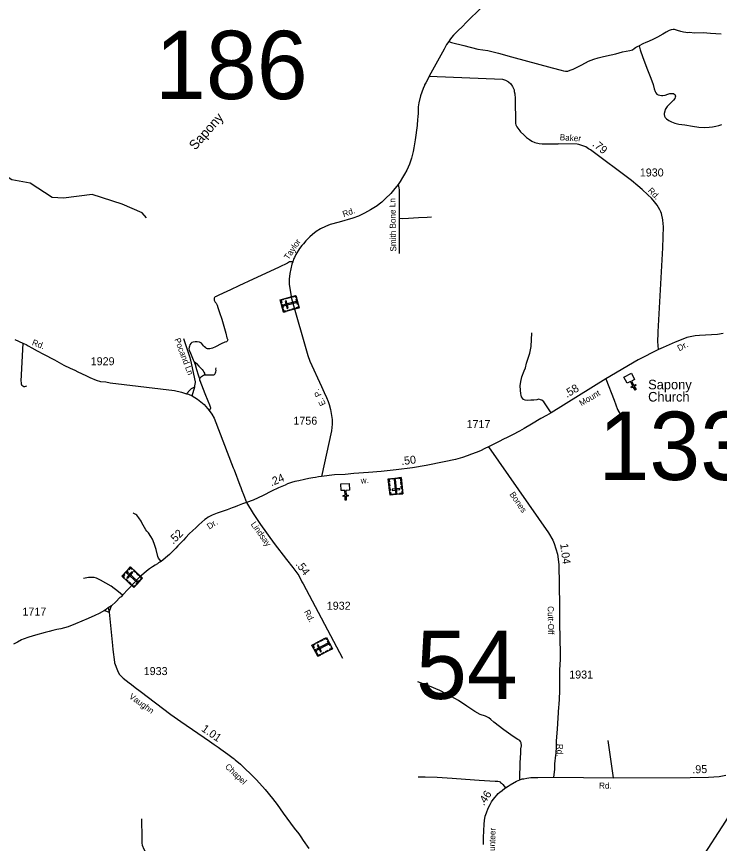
# Model space of a CAD drawing. Extents: x 2220236 to 2384410, y 720751 to 894131.
# Drawn here: x 2299448 to 2310413, y 774975 to 787885 of the extents above; entities that cross this region are included whole.
import ezdxf

# ---------------------------------------------------------------- set-up
doc = ezdxf.new("R2010")
doc.units = 0
doc.layers.add('Default', color=7, linetype='Continuous')

msp = doc.modelspace()

# ---------------------------------------------------------------- linework, layer by layer
at = {"layer": 'Default'}
for p, q in [((2305418, 784738), (2305415, 784186)), ((2302189, 781961), (2302228, 782105)), ((2300822, 778613), (2300894, 778584)), ((2308760, 776001), (2308675, 776581))]:
    msp.add_line(p, q, dxfattribs=at)
for points in [[(2306700, 788028), (2306467, 787795), (2306399, 787726), (2306337, 787665), (2306302, 787629), (2306266, 787594), (2306236, 787558), (2306209, 787523), (2306190, 787495), (2306157, 787450), (2306118, 787378), (2305885, 786954), (2305857, 786898), (2305832, 786848), (2305814, 786818), (2305810, 786806), (2305790, 786762), (2305750, 786649), (2305723, 786538), (2305717, 786505), (2305716, 786477), (2305714, 786449), (2305711, 786379), (2305707, 786315), (2305704, 786283), (2305704, 786261), (2305696, 786207), (2305699, 786185), (2305669, 785959), (2305646, 785835), (2305634, 785779), (2305625, 785737), (2305610, 785675), (2305577, 785582), (2305536, 785487), (2305501, 785422), (2305469, 785372), (2305434, 785311), (2305403, 785265), (2305375, 785233), (2305329, 785174), (2305285, 785124), (2305206, 785044), (2305147, 784988), (2305103, 784956), (2305073, 784932), (2305023, 784897), (2304972, 784867), (2304876, 784813), (2304781, 784768), (2304696, 784736), (2304483, 784677), (2304341, 784639), (2304267, 784609), (2304191, 784569), (2304123, 784527), (2304064, 784480), (2304024, 784445), (2303989, 784410), (2303960, 784382), (2303925, 784338), (2303897, 784308), (2303862, 784264), (2303805, 784169), (2303784, 784125), (2303771, 784095), (2303756, 784054), (2303743, 784017), (2303726, 783947), (2303713, 783873), (2303699, 783784), (2303700, 783706), (2303739, 783481), (2303992, 782594), (2304025, 782504), (2304205, 782109), (2304247, 782015), (2304285, 781935), (2304308, 781873), (2304326, 781826), (2304345, 781750), (2304371, 781594), (2304371, 781521), (2304364, 781418), (2304204, 780704)], [(2310440, 787609), (2310276, 787620), (2310159, 787629), (2310027, 787626), (2309939, 787635), (2309921, 787633), (2309891, 787636), (2309852, 787640), (2309809, 787651), (2309759, 787667), (2309712, 787680), (2309690, 787680), (2309659, 787677), (2309631, 787667), (2309581, 787642), (2309531, 787608), (2309448, 787562), (2309383, 787530), (2309307, 787495), (2309265, 787481), (2309216, 787459), (2309159, 787427)], [(2306190, 787495), (2306234, 787481), (2306428, 787432), (2306643, 787378), (2306798, 787353), (2306965, 787314), (2307172, 787257), (2307806, 787083), (2307945, 787046), (2307981, 787037), (2308014, 787033), (2308048, 787034), (2308085, 787046), (2308129, 787063), (2308267, 787133), (2308373, 787187), (2308454, 787219), (2308519, 787240), (2308584, 787257), (2308652, 787269), (2308798, 787305), (2308903, 787335), (2309015, 787353), (2309055, 787367), (2309082, 787388), (2309103, 787402), (2309118, 787411), (2309159, 787427)], [(2309159, 787427), (2309175, 787364), (2309216, 787246), (2309290, 787051), (2309343, 786921), (2309380, 786825), (2309397, 786757), (2309409, 786715), (2309422, 786696), (2309439, 786674), (2309458, 786661), (2309485, 786657), (2309507, 786652), (2309532, 786654), (2309568, 786659), (2309607, 786674), (2309642, 786683), (2309664, 786683), (2309681, 786683), (2309698, 786681), (2309708, 786671), (2309722, 786661), (2309727, 786642), (2309722, 786625), (2309720, 786603), (2309695, 786581), (2309647, 786529), (2309598, 786478), (2309568, 786434), (2309559, 786407), (2309551, 786373), (2309551, 786353), (2309556, 786331), (2309568, 786307), (2309585, 786287), (2309622, 786260), (2309664, 786241), (2309717, 786219), (2309781, 786206), (2309872, 786192), (2309994, 786172), (2310092, 786157), (2310175, 786152), (2310251, 786157), (2310304, 786165), (2310358, 786175), (2310405, 786184), (2310449, 786197)], [(2305885, 786954), (2307030, 786905), (2307074, 786893), (2307125, 786864), (2307157, 786832), (2307183, 786793), (2307210, 786739), (2307212, 786715), (2307223, 786677), (2307227, 786603), (2307234, 786214), (2307238, 786192), (2307252, 786164), (2307299, 786098), (2307311, 786084), (2307361, 786039), (2307402, 785999), (2307450, 785964), (2307487, 785940), (2307531, 785919), (2307601, 785904), (2307647, 785898), (2307895, 785899)], [(2301473, 784744), (2301406, 784820), (2301096, 784958), (2300628, 785109), (2300179, 785048), (2300004, 785061), (2299660, 785283), (2299376, 785337), (2299074, 785528), (2298880, 785708), (2298713, 785789), (2297953, 785949), (2297647, 785870), (2297517, 785867), (2297390, 785912), (2297170, 785999), (2297067, 786022), (2296687, 786025), (2296537, 786009), (2296397, 785849), (2296314, 785813), (2296248, 785813)], [(2309462, 782686), (2309456, 782749), (2309456, 782771), (2309454, 782791), (2309460, 782965), (2309531, 784273), (2309540, 784605), (2309537, 784651), (2309531, 784713), (2309508, 784809), (2309500, 784834), (2309485, 784868), (2309442, 784938), (2309402, 784993), (2309353, 785047), (2309297, 785104), (2309210, 785183), (2309139, 785240), (2309040, 785325), (2308400, 785804), (2308373, 785818), (2308327, 785849), (2308297, 785863), (2308219, 785886), (2308195, 785892), (2307895, 785899)], [(2305403, 785265), (2305410, 785212), (2305418, 785177), (2305419, 785089), (2305418, 784738)], [(2305418, 784738), (2305471, 784733), (2305564, 784735), (2305717, 784747), (2305855, 784752), (2305921, 784759)], [(2303756, 784054), (2303723, 784058), (2303708, 784053), (2303674, 784035), (2303545, 783972), (2303330, 783874), (2303139, 783784), (2302917, 783682), (2302787, 783619), (2302674, 783565), (2302592, 783530), (2302561, 783514), (2302547, 783507), (2302538, 783500), (2302533, 783488), (2302533, 783473), (2302533, 783457), (2302538, 783444), (2302548, 783428), (2302561, 783408), (2302577, 783380), (2302590, 783340), (2302614, 783264), (2302650, 783159), (2302683, 783053), (2302711, 782944), (2302731, 782870), (2302742, 782837), (2302741, 782828), (2302736, 782819), (2302723, 782809), (2302697, 782799), (2302638, 782774), (2302554, 782728), (2302507, 782709), (2302483, 782703), (2302466, 782699), (2302442, 782697), (2302428, 782698), (2302413, 782702), (2302400, 782713), (2302382, 782728), (2302366, 782746), (2302347, 782765), (2302332, 782786), (2302301, 782799), (2302264, 782807), (2302235, 782806), (2302203, 782803), (2302185, 782794), (2302169, 782779), (2302153, 782759), (2302144, 782740), (2302139, 782721), (2302138, 782698), (2302141, 782674), (2302160, 782628), (2302183, 782579), (2302203, 782528), (2302216, 782506)], [(2299422, 782841), (2299548, 782788), (2299597, 782764), (2299631, 782743), (2299685, 782713), (2299770, 782667), (2299869, 782615), (2300039, 782524), (2300188, 782444), (2300286, 782393), (2300358, 782362), (2300403, 782340), (2300527, 782279), (2300590, 782248), (2300690, 782208), (2300756, 782187), (2300839, 782181), (2300909, 782168), (2301911, 782048), (2302022, 782022), (2302102, 781996), (2302131, 781988), (2302189, 781961), (2302271, 781913), (2302373, 781829), (2302455, 781734), (2302495, 781676), (2302529, 781613), (2302827, 780838), (2302842, 780807), (2302934, 780568), (2302946, 780534), (2302963, 780486), (2302987, 780421), (2303034, 780298)], [(2302228, 782105), (2302232, 782119), (2302239, 782173), (2302239, 782183), (2302166, 782521), (2302149, 782574), (2302056, 782851)], [(2307786, 781698), (2307673, 781870), (2307644, 781896), (2307622, 781903), (2307594, 781909), (2307563, 781900), (2307516, 781896), (2307471, 781895), (2307425, 781893), (2307381, 781897), (2307357, 781908), (2307339, 781926), (2307328, 781949), (2307321, 781973), (2307315, 781994), (2307308, 782050), (2307306, 782122), (2307315, 782188), (2307324, 782234), (2307332, 782258), (2307366, 782356), (2307386, 782402), (2307405, 782472), (2307432, 782549), (2307457, 782631), (2307475, 782735), (2307486, 782949)], [(2310471, 782938), (2310381, 782922), (2310103, 782906), (2310037, 782900), (2309981, 782892), (2309905, 782876), (2309840, 782848), (2309724, 782803), (2309535, 782717), (2309462, 782686)], [(2299548, 782788), (2299516, 782194), (2299521, 782170), (2299521, 782150), (2299525, 782136), (2299531, 782128), (2299563, 782109), (2299575, 782109), (2299591, 782113), (2299611, 782121)], [(2309462, 782686), (2309146, 782528), (2308641, 782230), (2307786, 781698), (2307713, 781657), (2307629, 781612), (2307482, 781521), (2307368, 781452), (2307296, 781411), (2307185, 781354), (2307103, 781313), (2307046, 781286), (2306976, 781250), (2306813, 781168)], [(2302216, 782506), (2302256, 782467), (2302290, 782427), (2302323, 782393), (2302342, 782374), (2302358, 782354), (2302371, 782332), (2302381, 782316), (2302382, 782310), (2302383, 782299), (2302382, 782289)], [(2302216, 782506), (2302235, 782453), (2302255, 782374), (2302279, 782292), (2302296, 782243), (2302310, 782201)], [(2302382, 782289), (2302405, 782292), (2302436, 782293), (2302486, 782291), (2302507, 782289), (2302518, 782289), (2302525, 782292), (2302537, 782298), (2302544, 782303), (2302549, 782311), (2302554, 782322), (2302557, 782336), (2302561, 782359), (2302558, 782380), (2302561, 782399)], [(2302310, 782201), (2302309, 782228), (2302313, 782243), (2302319, 782252), (2302332, 782265), (2302348, 782277), (2302366, 782284), (2302382, 782289)], [(2302310, 782201), (2302332, 782136), (2302387, 781999), (2302432, 781886), (2302457, 781823), (2302468, 781794), (2302473, 781781), (2302473, 781767), (2302471, 781758), (2302462, 781743), (2302455, 781734)], [(2308641, 782230), (2308772, 781895), (2308822, 781750), (2308880, 781651), (2308984, 781415)], [(2302102, 781996), (2302149, 782051), (2302178, 782079), (2302228, 782105)], [(2306813, 781168), (2306756, 781140), (2306688, 781106), (2306620, 781081), (2306545, 781053), (2306477, 781026), (2306404, 781001), (2306295, 780972), (2306118, 780931), (2305839, 780875), (2305624, 780839), (2305368, 780807), (2305136, 780782), (2304937, 780766), (2304710, 780753), (2304576, 780737), (2304406, 780728), (2304204, 780704)], [(2306813, 781168), (2307748, 779827), (2307813, 779709), (2307834, 779659), (2307886, 779490), (2307906, 779328), (2307918, 778692), (2307918, 778487), (2307916, 778397), (2307918, 778332), (2307923, 778264), (2307928, 777855), (2307919, 777681), (2307918, 777343), (2307908, 777138), (2307904, 777108), (2307882, 776758), (2307868, 776578), (2307866, 776489), (2307859, 776378), (2307857, 776354), (2307841, 776218), (2307838, 776130), (2307826, 776008)], [(2304204, 780704), (2304161, 780700), (2304113, 780691), (2304072, 780685), (2304007, 780671), (2303939, 780657), (2303852, 780637), (2303789, 780626), (2303737, 780610), (2303676, 780589), (2303638, 780571), (2303536, 780529), (2303424, 780476), (2303296, 780408), (2303137, 780337), (2303034, 780298)], [(2303034, 780298), (2302971, 780276), (2302895, 780248), (2302858, 780232), (2302812, 780215), (2302736, 780185), (2302577, 780133), (2302499, 780101), (2302468, 780083), (2302440, 780067), (2302411, 780046), (2302388, 780032), (2302341, 779993), (2302290, 779950), (2302245, 779904), (2302200, 779860), (2302142, 779809), (2302089, 779751), (2302051, 779708), (2302001, 779659), (2301966, 779620), (2301935, 779587), (2301904, 779556), (2301876, 779528), (2301832, 779486), (2301702, 779377), (2301665, 779356), (2301647, 779343), (2301613, 779319), (2301568, 779293), (2301521, 779261), (2301478, 779225), (2301433, 779190), (2301364, 779130), (2301103, 778853), (2301078, 778827), (2301060, 778813), (2300995, 778748), (2300931, 778687), (2300902, 778671), (2300875, 778652)], [(2303034, 780298), (2303140, 780125), (2303254, 779957), (2303465, 779657), (2303657, 779406), (2303757, 779281), (2303852, 779156), (2303900, 779059), (2303918, 779031), (2304531, 777868)], [(2301702, 779377), (2301663, 779430), (2301651, 779454), (2301626, 779566), (2301597, 779658), (2301568, 779725), (2301542, 779769), (2301505, 779825), (2301479, 779852), (2301465, 779872), (2301403, 779981), (2301391, 780007), (2301358, 780059), (2301324, 780103), (2301310, 780112), (2301280, 780128), (2301268, 780136)], [(2301103, 778853), (2301037, 778904), (2300924, 778993), (2300760, 779086), (2300696, 779116), (2300660, 779127), (2300618, 779129), (2300573, 779127), (2300493, 779110)], [(2300875, 778652), (2300854, 778635), (2300822, 778613), (2300736, 778567), (2300668, 778534), (2300563, 778486), (2300366, 778403), (2300252, 778359), (2300141, 778328), (2300075, 778313), (2300014, 778301), (2299959, 778283), (2299896, 778269), (2299745, 778229), (2299642, 778198), (2299552, 778165), (2299524, 778153), (2299462, 778120), (2299400, 778089)], [(2300875, 778652), (2300894, 778584), (2300946, 778065), (2300951, 778003), (2300975, 777808), (2300977, 777796), (2301022, 777674), (2301049, 777619), (2301084, 777584), (2301113, 777555), (2301206, 777482), (2301244, 777456), (2301299, 777411), (2301379, 777353), (2301856, 776991), (2302013, 776879), (2302456, 776571), (2302533, 776520), (2302593, 776478), (2302635, 776446), (2302744, 776370), (2302826, 776308), (2302845, 776294), (2302861, 776279), (2302940, 776213), (2303170, 775987), (2303186, 775975), (2303286, 775867), (2303328, 775819), (2303441, 775679), (2303476, 775631), (2303516, 775582), (2303609, 775449), (2303780, 775215), (2303850, 775126), (2303881, 775080), (2303918, 775022), (2304009, 774899)], [(2300894, 778584), (2300918, 778657), (2300931, 778687)], [(2307298, 775969), (2307298, 776065), (2307304, 776157), (2307306, 776228), (2307310, 776319), (2307314, 776385), (2307317, 776453), (2307323, 776501), (2307319, 776545), (2307312, 776568), (2307300, 776584), (2307268, 776599), (2307193, 776647), (2307048, 776749), (2306893, 776870), (2306849, 776910), (2306814, 776935), (2306765, 776960), (2306682, 776988), (2306598, 777034), (2306474, 777117), (2306342, 777209), (2306229, 777271), (2306053, 777361), (2305890, 777433), (2305709, 777499)], [(2311453, 776878), (2311350, 776706), (2311169, 776404), (2310909, 775982), (2310506, 775325), (2310120, 774722), (2309617, 773917), (2309477, 773688), (2308979, 772894), (2308528, 772165), (2308303, 771802), (2307636, 770733), (2307136, 769903), (2306871, 769438), (2306782, 769281)], [(2305714, 776015), (2305748, 776018), (2305823, 776017), (2306012, 776008), (2306242, 775994), (2306453, 775979), (2306667, 775963), (2306916, 775949), (2306956, 775946), (2306977, 775942), (2306991, 775937), (2307000, 775929), (2307015, 775919), (2307036, 775896), (2307053, 775869), (2307075, 775845)], [(2306731, 774961), (2306734, 775066), (2306742, 775274), (2306749, 775336), (2306761, 775401), (2306778, 775455), (2306806, 775526), (2306835, 775584), (2306860, 775625), (2306883, 775659), (2306914, 775699), (2306942, 775731), (2306964, 775754), (2306990, 775778), (2307023, 775803), (2307065, 775838), (2307075, 775845), (2307115, 775870), (2307149, 775893), (2307246, 775947), (2307298, 775969), (2307336, 775982), (2307362, 775986), (2307409, 775995), (2307470, 776003), (2307581, 776005), (2307826, 776008)], [(2307826, 776008), (2308760, 776001), (2309957, 776007), (2310242, 776012), (2310407, 776022), (2310511, 776042)], [(2301977, 774536), (2301952, 774553), (2301931, 774567), (2301876, 774607), (2301819, 774638), (2301689, 774680), (2301591, 774714), (2301546, 774744), (2301500, 774786), (2301478, 774813), (2301437, 774882), (2301415, 774941), (2301408, 774986), (2301406, 775010), (2301406, 775058), (2301405, 775362)]]:
    msp.add_lwpolyline(points, dxfattribs=at)
for points in [[(2303613, 783271), (2303560, 783463), (2303806, 783531), (2303859, 783339)], [(2303675, 783483), (2303634, 783471), (2303631, 783482), (2303672, 783494)], [(2303739, 783501), (2303697, 783489), (2303694, 783500), (2303736, 783512)], [(2303814, 783499), (2303803, 783496), (2303797, 783517), (2303759, 783506), (2303756, 783517), (2303806, 783531)], [(2303602, 783474), (2303605, 783463), (2303574, 783455), (2303585, 783416), (2303574, 783413), (2303560, 783463)], [(2303594, 783342), (2303580, 783392), (2303591, 783395), (2303605, 783345)], [(2303613, 783384), (2303618, 783366), (2303813, 783420), (2303808, 783438)], [(2303668, 783328), (2303686, 783333), (2303655, 783447), (2303637, 783442)], [(2303850, 783371), (2303839, 783368), (2303845, 783347), (2303806, 783336), (2303809, 783325), (2303859, 783339)], [(2303832, 783391), (2303810, 783473), (2303821, 783476), (2303843, 783394)], [(2303655, 783282), (2303652, 783293), (2303621, 783285), (2303610, 783324), (2303600, 783321), (2303613, 783271)], [(2303727, 783302), (2303685, 783291), (2303682, 783302), (2303724, 783313)], [(2303791, 783320), (2303750, 783309), (2303747, 783320), (2303788, 783331)], [(2309090, 782221), (2309040, 782194), (2309076, 782127), (2309104, 782143), (2309112, 782129), (2309084, 782113), (2309113, 782060), (2309098, 782053), (2309070, 782106), (2309042, 782090), (2309034, 782104), (2309062, 782120), (2309026, 782187), (2308975, 782159), (2308924, 782253), (2309039, 782315)], [(2305473, 780435), (2305275, 780415), (2305248, 780668), (2305446, 780689)], [(2305281, 780671), (2305282, 780660), (2305260, 780658), (2305265, 780617), (2305253, 780616), (2305248, 780668)], [(2305390, 780671), (2305306, 780662), (2305305, 780674), (2305389, 780683)], [(2305361, 780453), (2305380, 780455), (2305359, 780657), (2305340, 780655)], [(2305413, 780685), (2305414, 780674), (2305436, 780676), (2305440, 780636), (2305452, 780637), (2305446, 780689)], [(2304642, 780491), (2304585, 780488), (2304589, 780412), (2304621, 780414), (2304621, 780398), (2304589, 780396), (2304592, 780336), (2304576, 780335), (2304573, 780395), (2304542, 780394), (2304541, 780410), (2304573, 780411), (2304569, 780487), (2304512, 780485), (2304507, 780591), (2304637, 780597)], [(2305267, 780597), (2305271, 780554), (2305260, 780553), (2305256, 780596)], [(2305274, 780532), (2305278, 780488), (2305267, 780487), (2305262, 780530)], [(2305425, 780499), (2305423, 780517), (2305306, 780505), (2305308, 780486)], [(2305453, 780619), (2305458, 780576), (2305447, 780575), (2305442, 780618)], [(2305460, 780552), (2305465, 780509), (2305454, 780508), (2305449, 780551)], [(2305270, 780458), (2305281, 780459), (2305285, 780427), (2305325, 780431), (2305326, 780420), (2305275, 780415)], [(2305399, 780428), (2305347, 780422), (2305346, 780434), (2305398, 780439)], [(2305468, 780478), (2305457, 780477), (2305460, 780445), (2305420, 780441), (2305421, 780430), (2305473, 780435)], [(2301092, 779146), (2301227, 779292), (2301414, 779118), (2301278, 778973)], [(2301142, 779200), (2301177, 779238), (2301186, 779230), (2301150, 779192)], [(2301259, 779262), (2301251, 779254), (2301228, 779276), (2301200, 779246), (2301192, 779254), (2301227, 779292)], [(2301305, 779204), (2301273, 779234), (2301281, 779242), (2301312, 779212)], [(2301123, 779116), (2301131, 779125), (2301107, 779146), (2301135, 779176), (2301127, 779184), (2301092, 779146)], [(2301178, 779066), (2301146, 779095), (2301154, 779104), (2301185, 779074)], [(2301169, 779129), (2301183, 779117), (2301263, 779203), (2301249, 779216)], [(2301187, 779206), (2301174, 779192), (2301323, 779054), (2301336, 779068)], [(2301353, 779159), (2301321, 779189), (2301329, 779197), (2301361, 779168)], [(2301391, 779094), (2301383, 779102), (2301398, 779118), (2301368, 779146), (2301376, 779154), (2301414, 779118)], [(2301227, 779020), (2301195, 779050), (2301203, 779058), (2301235, 779028)], [(2301301, 778997), (2301292, 779005), (2301277, 778988), (2301248, 779016), (2301240, 779008), (2301278, 778973)], [(2301309, 779022), (2301367, 779085), (2301375, 779077), (2301317, 779015)], [(2304150, 777897), (2304057, 778073), (2304283, 778192), (2304375, 778016)], [(2304298, 778162), (2304288, 778157), (2304278, 778176), (2304242, 778158), (2304237, 778168), (2304283, 778192)], [(2304096, 778093), (2304101, 778083), (2304073, 778068), (2304091, 778032), (2304082, 778027), (2304057, 778073)], [(2304166, 778117), (2304127, 778097), (2304122, 778107), (2304160, 778127)], [(2304125, 778007), (2304134, 777991), (2304313, 778085), (2304305, 778101)], [(2304191, 777965), (2304208, 777973), (2304153, 778078), (2304137, 778069)], [(2304224, 778148), (2304186, 778128), (2304180, 778138), (2304219, 778158)], [(2304339, 778061), (2304299, 778136), (2304309, 778141), (2304349, 778066)], [(2304116, 777962), (2304092, 778008), (2304102, 778014), (2304126, 777968)], [(2304188, 777917), (2304183, 777927), (2304155, 777912), (2304136, 777948), (2304126, 777943), (2304150, 777897)], [(2304254, 777952), (2304216, 777931), (2304210, 777942), (2304249, 777962)], [(2304314, 777983), (2304275, 777963), (2304270, 777973), (2304308, 777993)], [(2304360, 778045), (2304350, 778039), (2304360, 778020), (2304324, 778001), (2304330, 777991), (2304375, 778015)]]:
    msp.add_lwpolyline(points, close=True, dxfattribs=at)

# ---------------------------------------------------------------- texts
for s, height, p in [('186', 1066.3, (2301610, 786596)), ('1930', 125, (2309171, 785388)), ('1929', 125, (2300605, 782441)), ('Sapony', 150, (2309301, 782065)), ('Church', 150, (2309301, 781874)), ('133', 1066.3, (2308527, 780650)), ('1756', 125, (2303767, 781513)), ('1717', 125, (2306468, 781460)), ('1932', 125, (2304288, 778624)), ('1717', 125, (2299540, 778532)), ('54', 1066.3, (2305680, 777232)), ('1933', 125, (2301432, 777604)), ('1931', 125, (2308070, 777550))]:
    msp.add_text(s, height=height, dxfattribs=at).set_placement(p)
for s, height, rotation, p in [('Sapony', 150, 48.5924, (2302236, 785790)), ('Baker', 95, 356.0247, (2307920, 785956)), ('.79', 125, 320.8468, (2308421, 785875)), ('Rd.', 95, 314.5486, (2309289, 785159)), ('Smith Bone Ln', 95, 91.0225, (2305372, 784217)), ('Rd.', 95, 19.3542, (2304553, 784752)), ('Taylor', 95, 55.9363, (2303690, 784079)), ('Rd.', 95, 339.2946, (2299681, 782760)), ('Pocand Ln', 95, 290.8424, (2301909, 782845)), ('Dr.', 95, 28.5338, (2309788, 782657)), ('E. P.', 95, 115.0526, (2304275, 781833)), ('.58', 125, 30.6988, (2308034, 781929)), ('Mount', 95, 30.6988, (2308260, 781800)), ('.50', 125, 7.0672, (2305455, 780881)), ('.24', 125, 22.5927, (2303424, 780550)), ('w.', 95, 3.7723, (2304820, 780593)), ('Bones', 95, 304.4528, (2307134, 780425)), ('Dr.', 95, 33.0662, (2302456, 779874)), ('Lindsay', 95, 305.4655, (2303097, 779958)), ('.52', 125, 44.3109, (2301892, 779640)), ('1.04', 125, 277.3196, (2307928, 779652)), ('.54', 125, 307.3489, (2303796, 779332)), ('Rd.', 95, 297.7622, (2303929, 778593)), ('Cutt-Off', 95, 270.7547, (2307734, 778680)), ('Vaughn', 95, 324.3635, (2301195, 777250)), ('1.01', 125, 325.162, (2302322, 776740)), ('Rd.', 95, 269.0318, (2307879, 776531)), ('Chapel', 95, 316.3654, (2302693, 776163)), ('.95', 125, 1.1541, (2309991, 776070)), ('Rd.', 95, 359.4088, (2308535, 775832)), ('.46', 125, 56.3276, (2306738, 775555)), ('Volunteer', 95, 88.4885, (2306907, 774674))]:
    msp.add_text(s, height=height, rotation=rotation, dxfattribs=at).set_placement(p)

doc.saveas('drawing.dxf')
